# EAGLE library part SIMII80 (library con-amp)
AMP connector
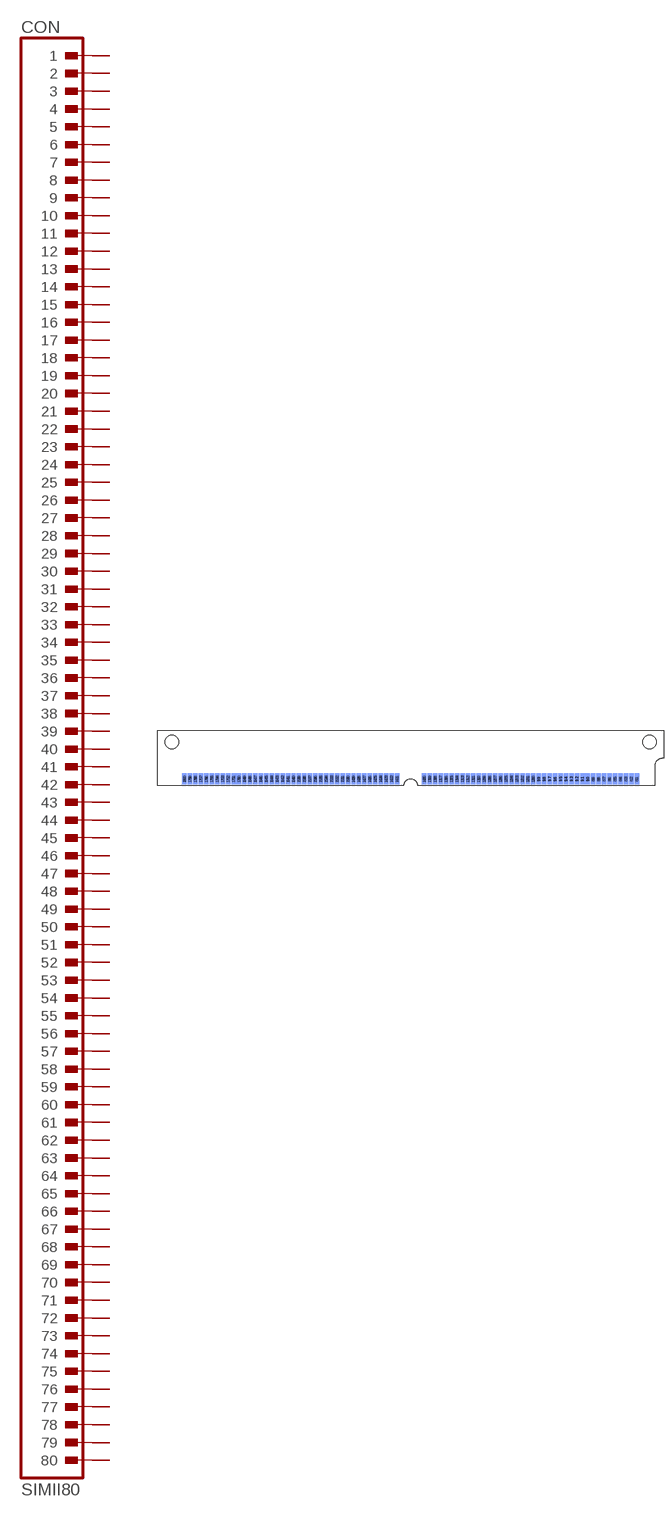
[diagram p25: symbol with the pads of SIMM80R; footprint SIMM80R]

Designator prefix CON

## SIMII80 (OC_FARNELL: unknown; OC_NEWARK: unknown)  [SIMM80R]
1  1  pas
2  2  pas
3  3  pas
4  4  pas
5  5  pas
6  6  pas
7  7  pas
8  8  pas
9  9  pas
10  10  pas
11  11  pas
12  12  pas
13  13  pas
14  14  pas
15  15  pas
16  16  pas
17  17  pas
18  18  pas
19  19  pas
20  20  pas
21  21  pas
22  22  pas
23  23  pas
24  24  pas
25  25  pas
26  26  pas
27  27  pas
28  28  pas
29  29  pas
30  30  pas
31  31  pas
32  32  pas
33  33  pas
34  34  pas
35  35  pas
36  36  pas
37  37  pas
38  38  pas
39  39  pas
40  40  pas
41  41  pas
42  42  pas
43  43  pas
44  44  pas
45  45  pas
46  46  pas
47  47  pas
48  48  pas
49  49  pas
50  50  pas
51  51  pas
52  52  pas
53  53  pas
54  54  pas
55  55  pas
56  56  pas
57  57  pas
58  58  pas
59  59  pas
60  60  pas
61  61  pas
62  62  pas
63  63  pas
64  64  pas
65  65  pas
66  66  pas
67  67  pas
68  68  pas
69  69  pas
70  70  pas
71  71  pas
72  72  pas
73  73  pas
74  74  pas
75  75  pas
76  76  pas
77  77  pas
78  78  pas
79  79  pas
80  80  pas
81  81  pas
82  82  pas
83  83  pas
84  84  pas
85  85  pas
86  86  pas
87  87  pas
88  88  pas
89  89  pas
90  90  pas
91  91  pas
92  92  pas
93  93  pas
94  94  pas
95  95  pas
96  96  pas
97  97  pas
98  98  pas
99  99  pas
100  100  pas
101  101  pas
102  102  pas
103  103  pas
104  104  pas
105  105  pas
106  106  pas
107  107  pas
108  108  pas
109  109  pas
110  110  pas
111  111  pas
112  112  pas
113  113  pas
114  114  pas
115  115  pas
116  116  pas
117  117  pas
118  118  pas
119  119  pas
120  120  pas
121  121  pas
122  122  pas
123  123  pas
124  124  pas
125  125  pas
126  126  pas
127  127  pas
128  128  pas
129  129  pas
130  130  pas
131  131  pas
132  132  pas
133  133  pas
134  134  pas
135  135  pas
136  136  pas
137  137  pas
138  138  pas
139  139  pas
140  140  pas
141  141  pas
142  142  pas
143  143  pas
144  144  pas
145  145  pas
146  146  pas
147  147  pas
148  148  pas
149  149  pas
150  150  pas
151  151  pas
152  152  pas
153  153  pas
154  154  pas
155  155  pas
156  156  pas
157  157  pas
158  158  pas
159  159  pas
160  160  pas

## Footprint SIMM80R (pad centres in mm)
SIMM II 80 Right Polarization
smd 1.041 x 2.54: 1 52.705,-8.636; 2 51.435,-8.636; 3 50.165,-8.636; 4 48.895,-8.636; 5 47.625,-8.636; 6 46.355,-8.636; 7 45.085,-8.636; 8 43.815,-8.636; 9 42.545,-8.636; 10 41.275,-8.636; 11 40.005,-8.636; 12 38.735,-8.636; 13 37.465,-8.636; 14 36.195,-8.636; 15 34.925,-8.636; 16 33.655,-8.636; 17 32.385,-8.636; 18 31.115,-8.636; 19 29.845,-8.636; 20 28.575,-8.636; 21 27.305,-8.636; 22 26.035,-8.636; 23 24.765,-8.636; 24 23.495,-8.636; 25 22.225,-8.636; 26 20.955,-8.636; 27 19.685,-8.636; 28 18.415,-8.636; 29 17.145,-8.636; 30 15.875,-8.636; 31 14.605,-8.636; 32 13.335,-8.636; 33 12.065,-8.636; 34 10.795,-8.636; 35 9.525,-8.636; 36 8.255,-8.636; 37 6.985,-8.636; 38 5.715,-8.636; 39 4.445,-8.636; 40 3.175,-8.636; 41 -3.175,-8.636; 42 -4.445,-8.636; 43 -5.715,-8.636; 44 -6.985,-8.636; 45 -8.255,-8.636; 46 -9.525,-8.636; 47 -10.795,-8.636; 48 -12.065,-8.636; 49 -13.335,-8.636; 50 -14.605,-8.636; 51 -15.875,-8.636; 52 -17.145,-8.636; 53 -18.415,-8.636; 54 -19.685,-8.636; 55 -20.955,-8.636; 56 -22.225,-8.636; 57 -23.495,-8.636; 58 -24.765,-8.636; 59 -26.035,-8.636; 60 -27.305,-8.636; 61 -28.575,-8.636; 62 -29.845,-8.636; 63 -31.115,-8.636; 64 -32.385,-8.636; 65 -33.655,-8.636; 66 -34.925,-8.636; 67 -36.195,-8.636; 68 -37.465,-8.636; 69 -38.735,-8.636; 70 -40.005,-8.636; 71 -41.275,-8.636; 72 -42.545,-8.636; 73 -43.815,-8.636; 74 -45.085,-8.636; 75 -46.355,-8.636; 76 -47.625,-8.636; 77 -48.895,-8.636; 78 -50.165,-8.636; 79 -51.435,-8.636; 80 -52.705,-8.636
smd 1.041 x 2.54 bottom: 81 52.705,-8.636; 82 51.435,-8.636; 83 50.165,-8.636; 84 48.895,-8.636; 85 47.625,-8.636; 86 46.355,-8.636; 87 45.085,-8.636; 88 43.815,-8.636; 89 42.545,-8.636; 90 41.275,-8.636; 91 40.005,-8.636; 92 38.735,-8.636; 93 37.465,-8.636; 94 36.195,-8.636; 95 34.925,-8.636; 96 33.655,-8.636; 97 32.385,-8.636; 98 31.115,-8.636; 99 29.845,-8.636; 100 28.575,-8.636; 101 27.305,-8.636; 102 26.035,-8.636; 103 24.765,-8.636; 104 23.495,-8.636; 105 22.225,-8.636; 106 20.955,-8.636; 107 19.685,-8.636; 108 18.415,-8.636; 109 17.145,-8.636; 110 15.875,-8.636; 111 14.605,-8.636; 112 13.335,-8.636; 113 12.065,-8.636; 114 10.795,-8.636; 115 9.525,-8.636; 116 8.255,-8.636; 117 6.985,-8.636; 118 5.715,-8.636; 119 4.445,-8.636; 120 3.175,-8.636; 121 -3.175,-8.636; 122 -4.445,-8.636; 123 -5.715,-8.636; 124 -6.985,-8.636; 125 -8.255,-8.636; 126 -9.525,-8.636; 127 -10.795,-8.636; 128 -12.065,-8.636; 129 -13.335,-8.636; 130 -14.605,-8.636; 131 -15.875,-8.636; 132 -17.145,-8.636; 133 -18.415,-8.636; 134 -19.685,-8.636; 135 -20.955,-8.636; 136 -22.225,-8.636; 137 -23.495,-8.636; 138 -24.765,-8.636; 139 -26.035,-8.636; 140 -27.305,-8.636; 141 -28.575,-8.636; 142 -29.845,-8.636; 143 -31.115,-8.636; 144 -32.385,-8.636; 145 -33.655,-8.636; 146 -34.925,-8.636; 147 -36.195,-8.636; 148 -37.465,-8.636; 149 -38.735,-8.636; 150 -40.005,-8.636; 151 -41.275,-8.636; 152 -42.545,-8.636; 153 -43.815,-8.636; 154 -45.085,-8.636; 155 -46.355,-8.636; 156 -47.625,-8.636; 157 -48.895,-8.636; 158 -50.165,-8.636; 159 -51.435,-8.636; 160 -52.705,-8.636
hole 3.175 at -55.677,0
hole 3.175 at 55.677,0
